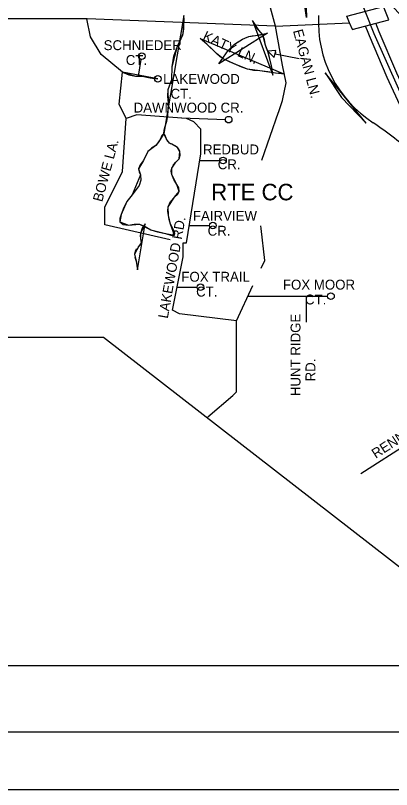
# Model space of a CAD drawing. Extents: x 5.01 to 9.58, y 0.27 to 3.39.
# Drawn here: x 6.828 to 7.24, y 0.321 to 1.17 of the extents above; entities that cross this region are included whole.
import ezdxf

# ---------------------------------------------------------------- set-up
doc = ezdxf.new("R2010")
doc.units = 0
for name, color, linetype in [('Level 7', 7, 'Continuous'), ('MO_001_NOSHOW', 7, 'Continuous'), ('MO_001_VIEW_99', 7, 'Continuous'), ('MO_001_VIEW_PV', 7, 'Continuous')]:
    doc.layers.add(name, color=color, linetype=linetype)

msp = doc.modelspace()

# ---------------------------------------------------------------- linework, layer by layer
at = {"layer": 'Level 7'}
for p, q in [((6.06398, 0.81688), (6.92435, 0.81688)), ((6.92435, 0.81688), (7.38772, 0.45685)), ((6.06398, 0.45685), (7.38772, 0.45685)), ((5.30436, 0.3838), (8.26663, 0.3838))]:
    msp.add_line(p, q, dxfattribs=at)
at = {"layer": 'MO_001_NOSHOW'}
for points in [[(7.14679, 1.16775), (7.14226, 1.19829), (7.14173, 1.23358), (7.14648, 1.27622), (7.147, 1.30256), (7.14069, 1.34889)], [(7.49418, 0.91607), (7.43342, 0.91734), (7.3323, 0.9598), (7.26151, 1.05891), (7.22106, 1.14994), (7.18666, 1.23691)], [(6.99044, 1.0403), (6.99132, 1.04689), (6.99374, 1.05413), (6.99505, 1.06556), (6.99549, 1.07391), (6.99505, 1.08864), (6.99901, 1.09962), (6.99945, 1.11368), (7.00538, 1.13631), (7.00956, 1.14466), (7.01154, 1.15037), (7.01241, 1.16047), (7.01241, 1.16992)], [(7.10996, 1.10444), (7.10827, 1.11462), (7.10623, 1.12379), (7.1042, 1.13058), (7.10182, 1.13737), (7.09876, 1.14857), (7.09434, 1.154), (7.08755, 1.16453)], [(7.05055, 1.117), (7.06107, 1.13159), (7.06786, 1.13838), (7.07669, 1.14382), (7.08348, 1.14688), (7.09095, 1.14789), (7.10385, 1.15061)], [(7.12253, 1.10566), (7.11268, 1.10682), (7.09571, 1.10919), (7.08213, 1.11089), (7.0699, 1.11597), (7.05531, 1.12243), (7.04817, 1.1282), (7.03765, 1.13838), (7.03018, 1.14484)], [(6.94514, 1.10773), (6.95922, 1.10341), (6.96669, 1.10341), (6.97552, 1.10172), (6.98366, 1.10037)], [(7.16737, 1.10691), (7.18509, 1.07988), (7.21222, 1.05178)], [(6.98653, 1.03402), (6.98148, 1.02741), (6.97292, 1.0208), (6.96827, 1.01069), (6.96244, 1.00176), (6.96477, 0.99515), (6.95583, 0.973), (6.94999, 0.966), (6.94377, 0.95162), (6.94222, 0.94346), (6.95155, 0.93996), (6.9636, 0.94113), (6.97603, 0.93491), (6.99236, 0.93063), (7.00207, 0.92908), (6.9978, 0.94113), (6.99547, 0.95045), (6.99508, 0.96017), (7.00207, 0.97067), (7.00713, 0.97689), (7.00479, 0.98465), (6.99897, 0.99554), (6.99897, 1.00254), (7.00364, 1.00915), (7.00713, 1.01265), (7.0079, 1.0208), (7.00518, 1.02508), (6.99897, 1.02858), (6.99664, 1.02974), (6.99314, 1.03441), (6.99042, 1.04063), (6.98653, 1.03402)], [(6.96996, 0.94126), (6.96478, 0.93089), (6.96478, 0.92516), (6.9656, 0.92051), (6.96287, 0.91696), (6.95822, 0.90822), (6.96013, 0.90031), (6.9615, 0.89102)]]:
    msp.add_lwpolyline(points, close=True, dxfattribs=at)
at = {"layer": 'MO_001_VIEW_99'}
msp.add_line((5.01404, 0.3206), (9.57964, 0.3206), dxfattribs=at)
at = {"layer": 'MO_001_VIEW_PV'}
for p, q in [((7.19104, 1.16908), (7.23104, 1.17981)), ((6.90623, 1.16618), (6.8126, 1.16618)), ((7.11277, 1.15835), (6.90623, 1.16618)), ((7.19698, 1.15458), (7.23698, 1.16517)), ((7.11275, 1.1584), (7.19399, 1.16194)), ((7.12059, 1.11546), (7.11277, 1.15835)), ((7.11285, 1.12971), (7.11247, 1.12792)), ((6.96246, 1.10343), (6.96566, 1.12184)), ((7.11247, 1.12792), (7.13886, 1.12285)), ((7.09768, 1.01118), (7.11608, 1.06374)), ((7.00985, 1.05748), (7.05783, 1.05574)), ((7.02971, 1.01066), (7.0516, 1.01066)), ((7.01827, 0.93949), (7.04044, 0.93949)), ((7.00478, 0.87167), (7.02696, 0.87167)), ((7.06987, 0.83486), (7.0881, 0.87357)), ((7.08262, 0.86181), (7.16987, 0.86181)), ((7.14639, 0.86181), (7.14639, 0.83354)), ((7.20625, 0.66731), (7.2609, 0.70238))]:
    msp.add_line(p, q, dxfattribs=at)
for points in [[(7.11275, 1.1584), (7.10106, 1.20128), (7.09716, 1.21297)], [(7.23692, 1.1652), (7.23395, 1.17246), (7.23099, 1.17971)], [(6.94514, 1.10773), (6.92175, 1.12721), (6.91006, 1.14671), (6.90616, 1.1662)], [(6.9996, 1.10779), (6.99949, 1.11073), (6.99945, 1.11368), (7.00117, 1.12532), (7.00538, 1.13631), (7.00751, 1.14047), (7.00956, 1.14466), (7.01068, 1.14746), (7.01154, 1.15037), (7.01223, 1.15538), (7.01241, 1.16047), (7.01249, 1.1652), (7.01241, 1.16992)], [(7.19699, 1.15456), (7.19401, 1.16185), (7.19106, 1.16914)], [(7.10955, 1.10727), (7.10895, 1.11095), (7.10827, 1.11462), (7.10732, 1.11922), (7.10623, 1.12379), (7.10529, 1.12721), (7.1042, 1.13058), (7.10294, 1.13394), (7.10182, 1.13737), (7.10061, 1.14316), (7.09876, 1.14857), (7.09671, 1.15135), (7.09434, 1.154), (7.09237, 1.15655), (7.0906, 1.15923)], [(7.27342, 1.02393), (7.26458, 1.04002), (7.25627, 1.05633), (7.2351, 1.10184), (7.21564, 1.1477), (7.21345, 1.15302), (7.21127, 1.15836)], [(7.2846, 1.02792), (7.27538, 1.04458), (7.26674, 1.06151), (7.24574, 1.10667), (7.22646, 1.15217), (7.22455, 1.15678), (7.22265, 1.16139)], [(7.07103, 1.14059), (7.07382, 1.14225), (7.07669, 1.14382), (7.08003, 1.14555), (7.08348, 1.14688), (7.08718, 1.14753), (7.09095, 1.14789), (7.09467, 1.14845), (7.09836, 1.14923)], [(7.12253, 1.10566), (7.11759, 1.10619), (7.11268, 1.10682), (7.10422, 1.1081), (7.09571, 1.10919), (7.08883, 1.10975), (7.08213, 1.11089), (7.07597, 1.1132), (7.0699, 1.11597), (7.06243, 1.11895), (7.05531, 1.12243), (7.05161, 1.12513), (7.04817, 1.1282), (7.04292, 1.13332), (7.03765, 1.13838), (7.03396, 1.14166), (7.03018, 1.14484)], [(7.11247, 1.12792), (7.11324, 1.13151), (7.1044, 1.13077), (7.11127, 1.12392), (7.11285, 1.12971)], [(7.11596, 1.0634), (7.12056, 1.07654), (7.12445, 1.09603), (7.12056, 1.11552)], [(6.94904, 1.05705), (6.94124, 1.07264), (6.94514, 1.10773)], [(6.94514, 1.10773), (6.95197, 1.1048), (6.95922, 1.10341), (6.96296, 1.10344), (6.96669, 1.10341), (6.97112, 1.10272), (6.97552, 1.10172), (6.9778, 1.10128), (6.98008, 1.1009)], [(6.99044, 1.0403), (6.99071, 1.04363), (6.99132, 1.04689), (6.99252, 1.05053), (6.99374, 1.05413), (6.99467, 1.05979), (6.99505, 1.06556), (6.99538, 1.06974), (6.99549, 1.07391), (6.99486, 1.08136), (6.99505, 1.08864), (6.99536, 1.08981), (6.99572, 1.09098)], [(6.99722, 0.92384), (6.92566, 0.9401), (6.92566, 0.9596), (6.94514, 0.99858), (6.94904, 1.05705)], [(7.0114, 0.92062), (7.0153, 0.92062), (7.0309, 1.01807), (7.0309, 1.04536), (7.02311, 1.05315), (7.0153, 1.05705), (6.96073, 1.06094), (6.94904, 1.05705)], [(6.96996, 0.94126), (6.96667, 0.93643), (6.96478, 0.93089), (6.96446, 0.92806), (6.96478, 0.92516), (6.96495, 0.92447), (6.96516, 0.92379)], [(7.09717, 0.89286), (7.10106, 0.90112), (7.09716, 0.93621), (7.09675, 0.93905)], [(6.96561, 0.92195), (6.96567, 0.9212), (6.9656, 0.92051), (6.96455, 0.91868), (6.96287, 0.91696), (6.96249, 0.91657), (6.96211, 0.91618)], [(7.06987, 0.83486), (7.00751, 0.84265), (6.99971, 0.84655), (7.0114, 0.90503), (7.0114, 0.92062)], [(6.96043, 0.91408), (6.95885, 0.91122), (6.95822, 0.90822), (6.95822, 0.90801), (6.95822, 0.90779)], [(6.95877, 0.90464), (6.95945, 0.90248), (6.96013, 0.90031), (6.9603, 0.89966), (6.96045, 0.899)], [(6.96099, 0.89592), (6.96127, 0.89347), (6.9615, 0.89102)], [(7.03869, 0.72962), (7.06597, 0.753), (7.06987, 0.75689), (7.06987, 0.83486)]]:
    msp.add_lwpolyline(points, dxfattribs=at)
msp.add_lwpolyline([(6.98653, 1.03402), (6.98425, 1.03052), (6.98148, 1.02741), (6.97696, 1.02422), (6.97292, 1.0208), (6.97061, 1.01597), (6.96827, 1.01069), (6.96458, 1.0062), (6.96244, 1.00176), (6.96329, 0.99855), (6.96477, 0.99515), (6.96532, 0.9893), (6.96343, 0.98353), (6.95583, 0.973), (6.95271, 0.96949), (6.94999, 0.966), (6.94665, 0.95933), (6.94377, 0.95162), (6.94222, 0.94723), (6.94222, 0.94346), (6.94588, 0.94075), (6.95155, 0.93996), (6.95793, 0.94079), (6.9636, 0.94113), (6.96989, 0.93853), (6.97603, 0.93491), (6.98353, 0.93253), (6.99236, 0.93063), (6.99821, 0.92906), (7.00207, 0.92908), (7.00238, 0.93091), (7.00129, 0.9339), (6.9978, 0.94113), (6.99625, 0.94594), (6.99547, 0.95045), (6.99487, 0.95533), (6.99508, 0.96017), (6.99761, 0.96575), (7.00207, 0.97067), (7.00521, 0.97363), (7.00713, 0.97689), (7.00672, 0.98071), (7.00479, 0.98465), (7.00142, 0.99005), (6.99897, 0.99554), (6.99849, 0.99904), (6.99897, 1.00254), (7.00082, 1.00611), (7.00364, 1.00915), (7.00553, 1.0108), (7.00713, 1.01265), (7.0084, 1.01656), (7.0079, 1.0208), (7.00681, 1.02314), (7.00518, 1.02508), (7.00227, 1.02707), (6.99897, 1.02858), (6.99776, 1.02913), (6.99664, 1.02974), (6.9946, 1.03163), (6.99314, 1.03441), (6.99183, 1.03843), (6.99042, 1.04063), (6.98829, 1.03828), (6.98653, 1.03402)], close=True, dxfattribs=at)
for centre in [(6.96633, 1.12539), (6.98367, 1.10036), (7.06144, 1.05564), (7.05523, 1.01073), (7.04405, 0.93953), (7.03064, 0.87172), (7.17356, 0.86186)]:
    msp.add_circle(centre, 0.00362, dxfattribs=at)
msp.add_arc((7.29113, 1.16263), 0.13135, 176.85542, 237.20673, dxfattribs=at)
msp.add_ellipse((6.98218, 0.69985), major_axis=(-0.27584, 0.32555), ratio=0.995955, start_param=4.851704, end_param=4.985582, dxfattribs=at)

# ---------------------------------------------------------------- texts
for s, height, rotation, p in [('KATY LN.', 0.01087, 335, (7.03208, 1.14362)), ('EAGAN LN.', 0.01087, 285, (7.13185, 1.15317)), ('BOWE LA.', 0.01087, 75, (6.92284, 0.96477)), ('LAKEWOOD RD.', 0.0108704, 80, (6.9947, 0.8369)), ('HUNT RIDGE', 0.01087, 90, (7.14017, 0.75228)), ('    RD.', 0.01087, 90, (7.15649, 0.75228)), ('RENNS LAKE', 0.01087, 33, (7.22264, 0.6834))]:
    msp.add_text(s, height=height, rotation=rotation, dxfattribs=at).set_placement(p)
for s, height, p in [('SCHNIEDER', 0.01087, (6.92445, 1.13193)), ('      CT.', 0.01087, (6.92445, 1.11563)), ('LAKEWOOD', 0.01087, (6.98964, 1.09493)), ('  CT.', 0.01087, (6.98964, 1.07862)), ('DAWNWOOD CR.', 0.0108704, (6.95727, 1.06342)), ('REDBUD', 0.01087, (7.03331, 1.01753)), ('    CR.', 0.01087, (7.03331, 1.00122)), ('RTE CC', 0.018117, (7.04231, 0.96714)), ('FAIRVIEW', 0.01087, (7.02222, 0.94466)), ('    CR.', 0.01087, (7.02222, 0.92835)), ('FOX TRAIL', 0.01087, (7.00961, 0.87783)), ('FOX MOOR', 0.01087, (7.12086, 0.86917)), ('    CT.', 0.01087, (7.00961, 0.86151)), ('      CT.', 0.01087, (7.12086, 0.85287))]:
    msp.add_text(s, height=height, dxfattribs=at).set_placement(p)

doc.saveas('drawing.dxf')
